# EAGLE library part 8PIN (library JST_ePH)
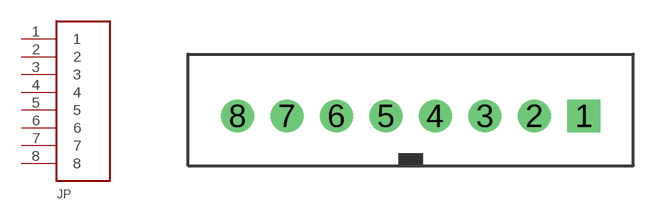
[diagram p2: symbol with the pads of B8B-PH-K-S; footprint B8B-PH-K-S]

Designator prefix JP

## 8PIN  [B8B-PH-K-S]
1  1
2  2
3  3
4  4
5  5
6  6
7  7
8  8

## Footprint B8B-PH-K-S (pad centres in mm)
drill 0.813 square: 1 7,0
drill 0.813 round: 2 5,0; 3 3,0; 4 1,0; 5 -1,0; 6 -3,0; 7 -5,0; 8 -7,0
